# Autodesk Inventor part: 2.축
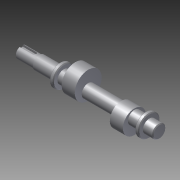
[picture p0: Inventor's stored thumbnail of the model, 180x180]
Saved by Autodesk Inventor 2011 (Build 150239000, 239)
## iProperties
Created: 2014-12
Part Number: 2.축
Document SubType Name: Modeling
Designer: user
Density: 1 g/cm^3
Author: user
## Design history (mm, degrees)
sketch "스케치1"
  geometry: L1 (-90, 0)-(90, 0); L2 (-90, 0)-(-90, 7.5); L3 (-90, 7.5)-(-66, 7.5); L4 (-66, 7.5)-(-66, 8.5); L5 (-66, 8.5)-(-39, 8.5); L6 (-39, 8.5)-(-39, 14); L7 (-39, 14)-(-34, 14); L8 (-34, 14)-(-34, 8.5); L9 (-34, 8.5)-(72, 8.5); L10 (72, 8.5)-(72, 14); L11 (72, 14)-(77, 14); L12 (77, 14)-(77, 8.5); L13 (77, 8.5)-(90, 8.5); L14 (90, 8.5)-(90, 0); 2 further points
  constraints: 28 end point, 11 parallel, 2 perpendicular, 1 coincident, 1 horizontal, 1 midpoint
  dimensions: "d0" = 180 distance of L1.start L1.end; "d1" = 17 diameter of L13 L1; "d2" = 15 diameter of L3 L1; "d3" = 17 diameter of L5 L1; "d4" = 28 diameter of L7 L1; "d5" = 28 diameter of L11 L1; "d6" = 17 diameter of L9 L1; "d7" = 24 distance of L2.end L3.end; "d8" = 27 distance of L4.end L5.end; "d9" = 5 distance of L6.end L7.end; "d10" = 5 distance of L10.end L11.end; "d11" = 13 distance of L12.end L13.end
revolve "회전1" sketch "스케치1" stored, may be unused: angle "d12" = 90 deg
node "작업 평면1"
sketch "스케치2"
  geometry: C1 r 15 at (5, 0); 1 further point
  constraints: 1 centre point, 1 horizontal alignment
  dimensions: "d14" = 30 diameter of C1; "d15" = 5 distance of point (0, 0) C1.centre
extrude "돌출1" join sketch "스케치2" stored distance "d16" = 17; taper "d17" = 0 deg
node "작업 평면2"
sketch "스케치3"
  geometry: C1 r 17.5 at (6, 0); 1 further point
  constraints: 1 centre point, 1 horizontal alignment
  dimensions: "d19" = 35 diameter of C1; "d20" = 6 distance of point (0, 0) C1.centre
extrude "돌출2" join sketch "스케치3" stored distance "d21" = 17; taper "d22" = 0 deg
chamfer "모따기1" distance "d23" = 1; stored, may be unused: second distance "d24" = 2, angle "d25" = 45 deg
chamfer "모따기2" distance "d26" = 1; stored, may be unused: second distance "d27" = 2, angle "d28" = 45 deg
chamfer "모따기3" distance "d29" = 1; stored, may be unused: second distance "d30" = 2, angle "d31" = 45 deg
chamfer "모따기4" distance "d32" = 1; stored, may be unused: second distance "d33" = 2, angle "d34" = 45 deg
chamfer "모따기5" distance "d35" = 1; stored, may be unused: second distance "d36" = 2, angle "d37" = 45 deg
chamfer "모따기6" distance "d38" = 1; stored, may be unused: second distance "d39" = 2, angle "d40" = 45 deg
node "작업 평면3"
sketch "스케치4"
  geometry: L1 (135.5, -4)-(135.5, -8.292) reference; L2 (135.5, -8.292)-(118.5, -8.292) reference; L3 (118.5, -8.292)-(118.5, -4) reference; L4 (118.5, -4)-(75.5, -4) reference; L5 (75.5, -4)-(75.5, -17.436) reference; L6 (75.5, -17.436)-(58.5, -17.436) reference; L7 (58.5, -17.436)-(58.5, -4) reference; L8 (58.5, -4)-(44, -4) reference; L9 (44, -4)-(44, -10.618) reference; L10 (43, -11.822)-(40, -11.822) reference; L11 (39, -10.618)-(39, -4) reference; L12 (39, -4)-(12, -4) reference; L13 (12, -4)-(12, 0) reference; L14 (-11, 0)-(12, 0) reference; L15 (150, -4)-(135.5, -4) reference; L16 (150, -10.618)-(150, -4) reference; L17 (154, -11.822)-(151, -11.822) reference; L18 (155, -4)-(155, -10.618) reference; L19 (167, -4)-(155, -4) reference; L20 (155, 4)-(167, 4) reference; L21 (155, 10.618)-(155, 4) reference; L22 (151, 11.822)-(154, 11.822) reference; L23 (150, 4)-(150, 10.618) reference; L24 (135.5, 4)-(150, 4) reference; L25 (135.5, 8.292)-(135.5, 4) reference; L26 (118.5, 8.292)-(135.5, 8.292) reference; L27 (118.5, 4)-(118.5, 8.292) reference; L28 (75.5, 4)-(118.5, 4) reference; L29 (75.5, 17.436)-(75.5, 4) reference; L30 (58.5, 17.436)-(75.5, 17.436) reference; L31 (58.5, 4)-(58.5, 17.436) reference; L32 (44, 4)-(58.5, 4) reference; L33 (44, 10.618)-(44, 4) reference; L34 (40, 11.822)-(43, 11.822) reference; L35 (39, 4)-(39, 10.618) reference; L36 (12, 4)-(39, 4) reference; L37 (12, 0)-(12, 4) reference; L38 (-12, 2.5)-(5.5, 2.5); L39 (5.5, 2.5)-(5.5, -2.5); L40 (5.5, -2.5)-(-12, -2.5); L41 (-12, -2.5)-(-12, 2.5); A1 r 2.5 centre (5.5, 0) between (5.5, -2.5) and (5.5, 2.5); 4 further points
  constraints: 8 end point, 3 point on circle, 2 horizontal alignment, 2 parallel, 2 tangent, 1 centre point, 1 horizontal, 1 midpoint, 1 perpendicular, 10 other
  dimensions: "d41" = 2.5 radius of A1; "d42" = 20 dimension on A1 L41; "d43" = 4 distance from line of L37 point (8, 0)
extrude "돌출3" cut sketch "스케치4" distance "d44" = 3; taper "d45" = 0 deg
node "솔리드1"
node "절단 모서리 투영1"
other parameters: "d13" = -41, "d18" = -79
